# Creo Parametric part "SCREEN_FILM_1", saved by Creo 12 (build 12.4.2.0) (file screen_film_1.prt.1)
Units: Custom; MM, KILOGRAM, SECS

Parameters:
  PTC_WM_ITERATION = "0"
  PTC_WM_VERSION = "-.0"
  PTC_WM_LIFECYCLE_STATE = "In Work"
  PTC_WM_LIFECYCLE = "MO_CADDocument"
  PTC_WM_CREATED_BY = "Maximilian Roepper (Z0017RMS: MO)"
  PTC_WM_CREATED_ON = "18-Sep-26 11:36:42 AM"
  PTC_WM_MODIFIED_BY = "Maximilian Roepper (Z0017RMS: MO)"
  PTC_WM_MODIFIED_ON = "18-Sep-26 11:36:46 AM"
  PDMLINKNUMBER = "PDM000071454990"
  PTC_WM_NAME = "screen_film_1.prt"
  PTC_WM_NUMBER = "PDM000071454990"

Other parameters: WEIGHT, WEIGHT_FACTOR, WEIGHT_ADD, _MASS_TEMP, _DIFF_TEMP, MC_ERRORS, SUPPLIER

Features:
  1. coordinate system
  2. datum plane "PRT_YZ"
  3. datum plane "PRT_XY"
  4. datum plane "PRT_XZ"
  5. coordinate system
  6. datum axis
  7. datum axis
  8. datum axis
  9. coordinate system
  10. imported feature

Other named items: PRT, SIEMENS_MO, DRW_VIEW_ORG, PRT_X, PRT_Y, PRT_Z, CS0, ROUGH_GROB

Layers: 00_STD_CSYS-KSYS, 01_STD_PLANES-EBENEN, 02_STD_AXES-ACHSEN, 03_STD_CSYS-KSYS, 24_IMPORT_FEAT-IMPORT_KE

Surfaces: 10 plane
